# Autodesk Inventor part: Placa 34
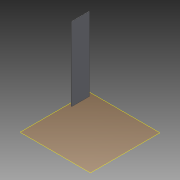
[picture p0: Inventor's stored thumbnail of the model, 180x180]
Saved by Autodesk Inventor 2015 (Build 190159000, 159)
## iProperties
Created: 2015-04
Part Number: Placa 34
Material: Generic
Document SubType Name: Modeling
Designer: suporte
Density: 1 g/cm^3
Appearance: Default
Author: suporte
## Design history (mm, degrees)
workplane "Work Plane1"
sketch "Sketch1"
  geometry: L1 (-912.5, 887.5)-(-787.5, 887.5) reference; L2 (-912.5, 887.5)-(-900, 887.5); L3 (-900, 887.5)-(-900, 377.5); L4 (-900, 377.5)-(-912.5, 377.5); L5 (-912.5, 377.5)-(-912.5, 887.5); L6 (-900, 362.5)-(-912.5, 362.5) reference; 1 further point
  constraints: 8 end point, 2 parallel, 1 horizontal, 1 perpendicular
  dimensions: "d0" = 12.5 distance of L3.end L4.end; "d1" = 15 distance between parallel lines of L6 L4
extrude "Extrusion1" new body sketch "Sketch1" distance "d2" = 2100; taper "d3" = 0 deg
body "Solid1"
node "Reference1"
node "Reference2"
